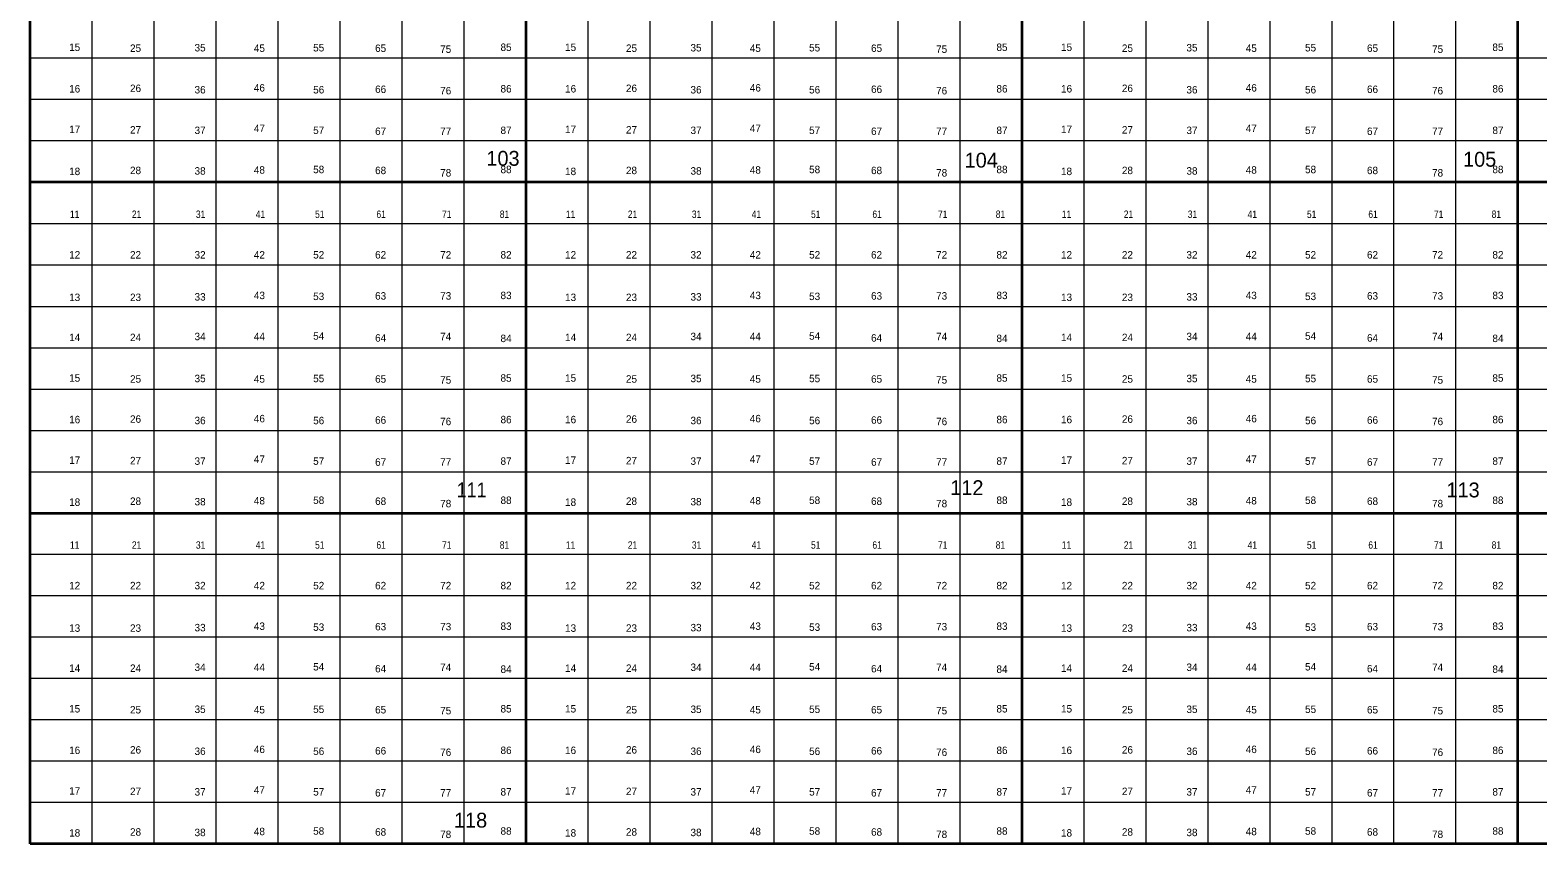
# Model space of a CAD drawing. Extents: x 639000 to 672000, y 222000 to 252000.
# Drawn here: x 642000 to 651120, y 224000 to 228920 of the extents above; entities that cross this region are included whole.
import ezdxf
from ezdxf.enums import TextEntityAlignment as Align

# ---------------------------------------------------------------- set-up
doc = ezdxf.new("R2010")
doc.units = 0
doc.header["$LTSCALE"] = 18
doc.layers.add('1', color=7, linetype='Continuous', lineweight=13)
doc.layers.add('2', color=7, linetype='Continuous')
doc.layers.add('29', color=7, linetype='Continuous')

msp = doc.modelspace()

# ---------------------------------------------------------------- linework, layer by layer
at = {"layer": '1', "lineweight": 35}
for p, q in [((648000, 224000), (648000, 252000)), ((651000, 224000), (651000, 252000)), ((645000, 224000), (645000, 250000)), ((642000, 224000), (642000, 248000)), ((663000, 228000), (642000, 228000)), ((642000, 226000), (663000, 226000)), ((663000, 224000), (642000, 224000))]:
    msp.add_line(p, q, dxfattribs=at)
at = {"layer": '1'}
for p, q in [((648375, 224000), (648375, 252000)), ((648750, 224000), (648750, 252000)), ((649125, 224000), (649125, 252000)), ((649500, 224000), (649500, 252000)), ((649875, 224000), (649875, 252000)), ((650250, 224000), (650250, 252000)), ((650625, 224000), (650625, 252000)), ((645375, 224000), (645375, 250000)), ((645750, 224000), (645750, 250000)), ((646125, 224000), (646125, 250000)), ((646500, 224000), (646500, 250000)), ((646875, 224000), (646875, 250000)), ((647250, 224000), (647250, 250000)), ((647625, 224000), (647625, 250000)), ((642375, 224000), (642375, 248000)), ((642750, 224000), (642750, 248000)), ((643125, 224000), (643125, 248000)), ((643500, 224000), (643500, 248000)), ((643875, 224000), (643875, 248000)), ((644250, 224000), (644250, 248000)), ((644625, 224000), (644625, 248000)), ((663000, 228750), (642000, 228750)), ((663000, 228500), (642000, 228500)), ((663000, 228250), (642000, 228250)), ((642000, 227750), (663000, 227750)), ((642000, 227500), (663000, 227500)), ((642000, 227250), (663000, 227250)), ((642000, 227000), (663000, 227000)), ((642000, 226750), (663000, 226750)), ((642000, 226500), (663000, 226500)), ((642000, 226250), (663000, 226250)), ((663000, 225750), (642000, 225750)), ((663000, 225500), (642000, 225500)), ((663000, 225250), (642000, 225250)), ((663000, 225000), (642000, 225000)), ((663000, 224750), (642000, 224750)), ((663000, 224500), (642000, 224500)), ((663000, 224250), (642000, 224250))]:
    msp.add_line(p, q, dxfattribs=at)

# ---------------------------------------------------------------- texts
at = {"layer": '2'}
for s, p in [('103', (644860.11, 228099.86)), ('104', (647752.99, 228088.81)), ('105', (650768.26, 228094.33)), ('112', (647666.21, 226108.58)), ('113', (650667.91, 226094.85)), ('118', (644664.07, 224098.13))]:
    msp.add_text(s, height=90, rotation=359.94, dxfattribs=at).set_placement(p, align=Align.CENTER)
at = {"layer": '2', "width": 0.9}
msp.add_text('111', height=90, rotation=359.94, dxfattribs=at).set_placement((644670.85, 226094.85), align=Align.CENTER)
at = {"layer": '29'}
for s, p in [('15', (642269.26, 228794.13)), ('25', (642637.51, 228788.35)), ('35', (643027.99, 228791.24)), ('45', (643386.72, 228788.35)), ('55', (643745.45, 228791.24)), ('65', (644120.05, 228788.36)), ('75', (644513.7, 228782.58)), ('85', (644878.78, 228794.13)), ('15', (645269.26, 228794.13)), ('25', (645637.51, 228788.35)), ('35', (646027.99, 228791.24)), ('45', (646386.72, 228788.35)), ('55', (646745.45, 228791.24)), ('65', (647120.05, 228788.36)), ('75', (647513.7, 228782.58)), ('85', (647878.78, 228794.13)), ('15', (648269.26, 228794.13)), ('25', (648637.51, 228788.35)), ('35', (649027.99, 228791.24)), ('45', (649386.72, 228788.35)), ('55', (649745.45, 228791.24)), ('65', (650120.05, 228788.36)), ('75', (650513.7, 228782.58)), ('85', (650878.78, 228794.13)), ('16', (642269.26, 228542.96)), ('26', (642637.51, 228545.85)), ('36', (643027.99, 228537.19)), ('46', (643386.72, 228548.74)), ('56', (643745.45, 228537.19)), ('66', (644120.05, 228540.08)), ('76', (644513.7, 228531.42)), ('86', (644878.78, 228542.96)), ('16', (645269.26, 228542.96)), ('26', (645637.51, 228545.85)), ('36', (646027.99, 228537.19)), ('46', (646386.72, 228548.74)), ('56', (646745.45, 228537.19)), ('66', (647120.05, 228540.08)), ('76', (647513.7, 228531.42)), ('86', (647878.78, 228542.96)), ('16', (648269.26, 228542.96)), ('26', (648637.51, 228545.85)), ('36', (649027.99, 228537.19)), ('46', (649386.72, 228548.74)), ('56', (649745.45, 228537.19)), ('66', (650120.05, 228540.08)), ('76', (650513.7, 228531.42)), ('86', (650878.78, 228542.96)), ('17', (642269.26, 228297.57)), ('27', (642637.51, 228294.69)), ('37', (643027.99, 228291.8)), ('47', (643386.72, 228303.35)), ('57', (643745.45, 228291.8)), ('67', (644120.05, 228286.03)), ('77', (644513.7, 228286.03)), ('87', (644878.78, 228291.8)), ('17', (645269.26, 228297.57)), ('27', (645637.51, 228294.69)), ('37', (646027.99, 228291.8)), ('47', (646386.72, 228303.35)), ('57', (646745.45, 228291.8)), ('67', (647120.05, 228286.03)), ('77', (647513.7, 228286.03)), ('87', (647878.78, 228291.8)), ('17', (648269.26, 228297.57)), ('27', (648637.51, 228294.69)), ('37', (649027.99, 228291.8)), ('47', (649386.72, 228303.35)), ('57', (649745.45, 228291.8)), ('67', (650120.05, 228286.03)), ('77', (650513.7, 228286.03)), ('87', (650878.78, 228291.8)), ('48', (643386.72, 228052.18)), ('58', (643745.45, 228055.07)), ('88', (644878.78, 228055.07)), ('48', (646386.72, 228052.18)), ('58', (646745.45, 228055.07)), ('88', (647878.78, 228055.07)), ('48', (649386.72, 228052.18)), ('58', (649745.45, 228055.07)), ('88', (650878.78, 228055.07)), ('18', (642269.25, 228043.52)), ('28', (642637.51, 228049.3)), ('38', (643027.99, 228046.41)), ('68', (644120.05, 228049.3)), ('78', (644513.7, 228034.86)), ('18', (645269.25, 228043.52)), ('28', (645637.51, 228049.3)), ('38', (646027.99, 228046.41)), ('68', (647120.05, 228049.3)), ('78', (647513.7, 228034.86)), ('18', (648269.25, 228043.52)), ('28', (648637.51, 228049.3)), ('38', (649027.99, 228046.41)), ('68', (650120.05, 228049.3)), ('78', (650513.7, 228034.86)), ('12', (642269.25, 227538.96)), ('22', (642637.51, 227538.96)), ('32', (643027.99, 227538.96)), ('42', (643386.72, 227538.96)), ('52', (643745.45, 227538.96)), ('62', (644120.05, 227538.96)), ('72', (644513.7, 227538.96)), ('82', (644878.78, 227538.96)), ('12', (645269.25, 227538.96)), ('22', (645637.51, 227538.96)), ('32', (646027.99, 227538.96)), ('42', (646386.72, 227538.96)), ('52', (646745.45, 227538.96)), ('62', (647120.05, 227538.96)), ('72', (647513.7, 227538.96)), ('82', (647878.78, 227538.96)), ('12', (648269.25, 227538.96)), ('22', (648637.51, 227538.96)), ('32', (649027.99, 227538.96)), ('42', (649386.72, 227538.96)), ('52', (649745.45, 227538.96)), ('62', (650120.05, 227538.96)), ('72', (650513.7, 227538.96)), ('82', (650878.78, 227538.96)), ('13', (642269.26, 227282.02)), ('23', (642637.51, 227282.02)), ('33', (643027.99, 227284.91)), ('43', (643386.72, 227293.57)), ('53', (643745.45, 227287.8)), ('63', (644120.05, 227290.68)), ('73', (644513.7, 227290.68)), ('83', (644878.78, 227293.57)), ('13', (645269.26, 227282.02)), ('23', (645637.51, 227282.02)), ('33', (646027.99, 227284.91)), ('43', (646386.72, 227293.57)), ('53', (646745.45, 227287.8)), ('63', (647120.05, 227290.68)), ('73', (647513.7, 227290.68)), ('83', (647878.78, 227293.57)), ('13', (648269.26, 227282.02)), ('23', (648637.51, 227282.02)), ('33', (649027.99, 227284.91)), ('43', (649386.72, 227293.57)), ('53', (649745.45, 227287.8)), ('63', (650120.05, 227290.68)), ('73', (650513.7, 227290.68)), ('83', (650878.78, 227293.57)), ('54', (643745.45, 227048.18)), ('54', (646745.45, 227048.18)), ('54', (649745.45, 227048.18)), ('14', (642269.26, 227039.52)), ('24', (642637.51, 227039.52)), ('34', (643027.99, 227045.29)), ('44', (643386.72, 227045.29)), ('64', (644120.05, 227036.63)), ('74', (644513.7, 227045.29)), ('84', (644878.78, 227033.74)), ('14', (645269.26, 227039.52)), ('24', (645637.51, 227039.52)), ('34', (646027.99, 227045.29)), ('44', (646386.72, 227045.29)), ('64', (647120.05, 227036.63)), ('74', (647513.7, 227045.29)), ('84', (647878.78, 227033.74)), ('14', (648269.26, 227039.52)), ('24', (648637.51, 227039.52)), ('34', (649027.99, 227045.29)), ('44', (649386.72, 227045.29)), ('64', (650120.05, 227036.63)), ('74', (650513.7, 227045.29)), ('84', (650878.78, 227033.74)), ('15', (642269.26, 226794.13)), ('25', (642637.51, 226788.35)), ('35', (643027.99, 226791.24)), ('45', (643386.72, 226788.35)), ('55', (643745.45, 226791.24)), ('65', (644120.05, 226788.36)), ('75', (644513.7, 226782.58)), ('85', (644878.78, 226794.13)), ('15', (645269.26, 226794.13)), ('25', (645637.51, 226788.35)), ('35', (646027.99, 226791.24)), ('45', (646386.72, 226788.35)), ('55', (646745.45, 226791.24)), ('65', (647120.05, 226788.36)), ('75', (647513.7, 226782.58)), ('85', (647878.78, 226794.13)), ('15', (648269.26, 226794.13)), ('25', (648637.51, 226788.35)), ('35', (649027.99, 226791.24)), ('45', (649386.72, 226788.35)), ('55', (649745.45, 226791.24)), ('65', (650120.05, 226788.36)), ('75', (650513.7, 226782.58)), ('85', (650878.78, 226794.13)), ('16', (642269.26, 226542.96)), ('26', (642637.51, 226545.85)), ('36', (643027.99, 226537.19)), ('46', (643386.72, 226548.74)), ('56', (643745.45, 226537.19)), ('66', (644120.05, 226540.08)), ('76', (644513.7, 226531.42)), ('86', (644878.78, 226542.96)), ('16', (645269.26, 226542.96)), ('26', (645637.51, 226545.85)), ('36', (646027.99, 226537.19)), ('46', (646386.72, 226548.74)), ('56', (646745.45, 226537.19)), ('66', (647120.05, 226540.08)), ('76', (647513.7, 226531.42)), ('86', (647878.78, 226542.96)), ('16', (648269.26, 226542.96)), ('26', (648637.51, 226545.85)), ('36', (649027.99, 226537.19)), ('46', (649386.72, 226548.74)), ('56', (649745.45, 226537.19)), ('66', (650120.05, 226540.08)), ('76', (650513.7, 226531.42)), ('86', (650878.78, 226542.96)), ('17', (642269.26, 226297.57)), ('27', (642637.51, 226294.69)), ('37', (643027.99, 226291.8)), ('47', (643386.72, 226303.35)), ('57', (643745.45, 226291.8)), ('67', (644120.05, 226286.03)), ('77', (644513.7, 226286.03)), ('87', (644878.78, 226291.8)), ('17', (645269.26, 226297.57)), ('27', (645637.51, 226294.69)), ('37', (646027.99, 226291.8)), ('47', (646386.72, 226303.35)), ('57', (646745.45, 226291.8)), ('67', (647120.05, 226286.03)), ('77', (647513.7, 226286.03)), ('87', (647878.78, 226291.8)), ('17', (648269.26, 226297.57)), ('27', (648637.51, 226294.69)), ('37', (649027.99, 226291.8)), ('47', (649386.72, 226303.35)), ('57', (649745.45, 226291.8)), ('67', (650120.05, 226286.03)), ('77', (650513.7, 226286.03)), ('87', (650878.78, 226291.8)), ('28', (642637.51, 226049.3)), ('38', (643027.99, 226046.41)), ('48', (643386.72, 226052.18)), ('58', (643745.45, 226055.07)), ('68', (644120.05, 226049.3)), ('88', (644878.78, 226055.07)), ('28', (645637.51, 226049.3)), ('38', (646027.99, 226046.41)), ('48', (646386.72, 226052.18)), ('58', (646745.45, 226055.07)), ('68', (647120.05, 226049.3)), ('88', (647878.78, 226055.07)), ('28', (648637.51, 226049.3)), ('38', (649027.99, 226046.41)), ('48', (649386.72, 226052.18)), ('58', (649745.45, 226055.07)), ('68', (650120.05, 226049.3)), ('88', (650878.78, 226055.07)), ('18', (642269.25, 226043.52)), ('78', (644513.7, 226034.86)), ('18', (645269.25, 226043.52)), ('78', (647513.7, 226034.86)), ('18', (648269.25, 226043.52)), ('78', (650513.7, 226034.86)), ('12', (642269.25, 225538.96)), ('22', (642637.51, 225538.96)), ('32', (643027.99, 225538.96)), ('42', (643386.72, 225538.96)), ('52', (643745.45, 225538.96)), ('62', (644120.05, 225538.96)), ('72', (644513.7, 225538.96)), ('82', (644878.78, 225538.96)), ('12', (645269.25, 225538.96)), ('22', (645637.51, 225538.96)), ('32', (646027.99, 225538.96)), ('42', (646386.72, 225538.96)), ('52', (646745.45, 225538.96)), ('62', (647120.05, 225538.96)), ('72', (647513.7, 225538.96)), ('82', (647878.78, 225538.96)), ('12', (648269.25, 225538.96)), ('22', (648637.51, 225538.96)), ('32', (649027.99, 225538.96)), ('42', (649386.72, 225538.96)), ('52', (649745.45, 225538.96)), ('62', (650120.05, 225538.96)), ('72', (650513.7, 225538.96)), ('82', (650878.78, 225538.96)), ('13', (642269.26, 225282.02)), ('23', (642637.51, 225282.02)), ('33', (643027.99, 225284.91)), ('43', (643386.72, 225293.57)), ('53', (643745.45, 225287.8)), ('63', (644120.05, 225290.68)), ('73', (644513.7, 225290.68)), ('83', (644878.78, 225293.57)), ('13', (645269.26, 225282.02)), ('23', (645637.51, 225282.02)), ('33', (646027.99, 225284.91)), ('43', (646386.72, 225293.57)), ('53', (646745.45, 225287.8)), ('63', (647120.05, 225290.68)), ('73', (647513.7, 225290.68)), ('83', (647878.78, 225293.57)), ('13', (648269.26, 225282.02)), ('23', (648637.51, 225282.02)), ('33', (649027.99, 225284.91)), ('43', (649386.72, 225293.57)), ('53', (649745.45, 225287.8)), ('63', (650120.05, 225290.68)), ('73', (650513.7, 225290.68)), ('83', (650878.78, 225293.57)), ('34', (643027.99, 225045.29)), ('44', (643386.72, 225045.29)), ('54', (643745.45, 225048.18)), ('74', (644513.7, 225045.29)), ('34', (646027.99, 225045.29)), ('44', (646386.72, 225045.29)), ('54', (646745.45, 225048.18)), ('74', (647513.7, 225045.29)), ('34', (649027.99, 225045.29)), ('44', (649386.72, 225045.29)), ('54', (649745.45, 225048.18)), ('74', (650513.7, 225045.29)), ('14', (642269.26, 225039.52)), ('24', (642637.51, 225039.52)), ('64', (644120.05, 225036.63)), ('84', (644878.78, 225033.74)), ('14', (645269.26, 225039.52)), ('24', (645637.51, 225039.52)), ('64', (647120.05, 225036.63)), ('84', (647878.78, 225033.74)), ('14', (648269.26, 225039.52)), ('24', (648637.51, 225039.52)), ('64', (650120.05, 225036.63)), ('84', (650878.78, 225033.74)), ('15', (642269.26, 224794.13)), ('25', (642637.51, 224788.35)), ('35', (643027.99, 224791.24)), ('45', (643386.72, 224788.35)), ('55', (643745.45, 224791.24)), ('65', (644120.05, 224788.36)), ('75', (644513.7, 224782.58)), ('85', (644878.78, 224794.13)), ('15', (645269.26, 224794.13)), ('25', (645637.51, 224788.35)), ('35', (646027.99, 224791.24)), ('45', (646386.72, 224788.35)), ('55', (646745.45, 224791.24)), ('65', (647120.05, 224788.36)), ('75', (647513.7, 224782.58)), ('85', (647878.78, 224794.13)), ('15', (648269.26, 224794.13)), ('25', (648637.51, 224788.35)), ('35', (649027.99, 224791.24)), ('45', (649386.72, 224788.35)), ('55', (649745.45, 224791.24)), ('65', (650120.05, 224788.36)), ('75', (650513.7, 224782.58)), ('85', (650878.78, 224794.13)), ('16', (642269.26, 224542.96)), ('26', (642637.51, 224545.85)), ('36', (643027.99, 224537.19)), ('46', (643386.72, 224548.74)), ('56', (643745.45, 224537.19)), ('66', (644120.05, 224540.08)), ('76', (644513.7, 224531.42)), ('86', (644878.78, 224542.96)), ('16', (645269.26, 224542.96)), ('26', (645637.51, 224545.85)), ('36', (646027.99, 224537.19)), ('46', (646386.72, 224548.74)), ('56', (646745.45, 224537.19)), ('66', (647120.05, 224540.08)), ('76', (647513.7, 224531.42)), ('86', (647878.78, 224542.96)), ('16', (648269.26, 224542.96)), ('26', (648637.51, 224545.85)), ('36', (649027.99, 224537.19)), ('46', (649386.72, 224548.74)), ('56', (649745.45, 224537.19)), ('66', (650120.05, 224540.08)), ('76', (650513.7, 224531.42)), ('86', (650878.78, 224542.96)), ('17', (642269.26, 224297.57)), ('27', (642637.51, 224294.69)), ('37', (643027.99, 224291.8)), ('47', (643386.72, 224303.35)), ('57', (643745.45, 224291.8)), ('67', (644120.05, 224286.03)), ('77', (644513.7, 224286.03)), ('87', (644878.78, 224291.8)), ('17', (645269.26, 224297.57)), ('27', (645637.51, 224294.69)), ('37', (646027.99, 224291.8)), ('47', (646386.72, 224303.35)), ('57', (646745.45, 224291.8)), ('67', (647120.05, 224286.03)), ('77', (647513.7, 224286.03)), ('87', (647878.78, 224291.8)), ('17', (648269.26, 224297.57)), ('27', (648637.51, 224294.69)), ('37', (649027.99, 224291.8)), ('47', (649386.72, 224303.35)), ('57', (649745.45, 224291.8)), ('67', (650120.05, 224286.03)), ('77', (650513.7, 224286.03)), ('87', (650878.78, 224291.8)), ('18', (642269.25, 224043.52)), ('28', (642637.51, 224049.3)), ('38', (643027.99, 224046.41)), ('48', (643386.72, 224052.18)), ('58', (643745.45, 224055.07)), ('68', (644120.05, 224049.3)), ('88', (644878.78, 224055.07)), ('18', (645269.25, 224043.52)), ('28', (645637.51, 224049.3)), ('38', (646027.99, 224046.41)), ('48', (646386.72, 224052.18)), ('58', (646745.45, 224055.07)), ('68', (647120.05, 224049.3)), ('88', (647878.78, 224055.07)), ('18', (648269.25, 224043.52)), ('28', (648637.51, 224049.3)), ('38', (649027.99, 224046.41)), ('48', (649386.72, 224052.18)), ('58', (649745.45, 224055.07)), ('68', (650120.05, 224049.3)), ('88', (650878.78, 224055.07)), ('78', (644513.7, 224034.86)), ('78', (647513.7, 224034.86)), ('78', (650513.7, 224034.86))]:
    msp.add_text(s, height=45, dxfattribs=at).set_placement(p, align=Align.CENTER)
at = {"layer": '29', "width": 0.85}
for s, p in [('11', (642269.26, 227784.35)), ('21', (642643.86, 227784.35)), ('31', (643031.16, 227784.35)), ('41', (643393.07, 227784.35)), ('51', (643751.8, 227784.35)), ('61', (644123.23, 227784.35)), ('71', (644520.05, 227784.35)), ('81', (644869.26, 227784.35)), ('11', (645269.26, 227784.35)), ('21', (645643.86, 227784.35)), ('31', (646031.16, 227784.35)), ('41', (646393.07, 227784.35)), ('51', (646751.8, 227784.35)), ('61', (647123.23, 227784.35)), ('71', (647520.05, 227784.35)), ('81', (647869.26, 227784.35)), ('11', (648269.26, 227784.35)), ('21', (648643.86, 227784.35)), ('31', (649031.16, 227784.35)), ('41', (649393.07, 227784.35)), ('51', (649751.8, 227784.35)), ('61', (650123.23, 227784.35)), ('71', (650520.05, 227784.35)), ('81', (650869.26, 227784.35)), ('11', (642269.26, 225784.35)), ('21', (642643.86, 225784.35)), ('31', (643031.16, 225784.35)), ('41', (643393.07, 225784.35)), ('51', (643751.8, 225784.35)), ('61', (644123.23, 225784.35)), ('71', (644520.05, 225784.35)), ('81', (644869.26, 225784.35)), ('11', (645269.26, 225784.35)), ('21', (645643.86, 225784.35)), ('31', (646031.16, 225784.35)), ('41', (646393.07, 225784.35)), ('51', (646751.8, 225784.35)), ('61', (647123.23, 225784.35)), ('71', (647520.05, 225784.35)), ('81', (647869.26, 225784.35)), ('11', (648269.26, 225784.35)), ('21', (648643.86, 225784.35)), ('31', (649031.16, 225784.35)), ('41', (649393.07, 225784.35)), ('51', (649751.8, 225784.35)), ('61', (650123.23, 225784.35)), ('71', (650520.05, 225784.35)), ('81', (650869.26, 225784.35))]:
    msp.add_text(s, height=45, dxfattribs=at).set_placement(p, align=Align.CENTER)

doc.saveas('drawing.dxf')
